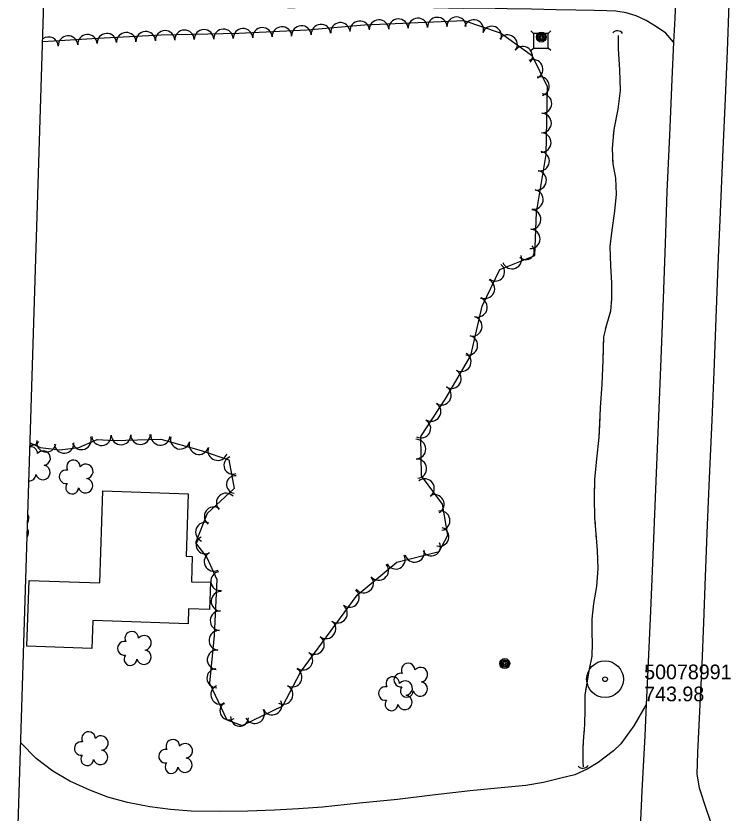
# Model space of a CAD drawing. Extents: x 591954 to 597000, y 198576 to 213500.
# Drawn here: x 593584.8 to 593879, y 199606.8 to 199932.5 of the extents above; entities that cross this region are included whole.
import ezdxf

# ---------------------------------------------------------------- set-up
doc = ezdxf.new("R2010")
doc.units = 0
for name, color, linetype in [('Level 11', 7, 'Continuous'), ('Level 12', 7, 'Continuous'), ('Level 14', 7, 'Continuous'), ('Level 15', 7, 'Continuous'), ('Level 17', 7, 'Continuous'), ('Level 18', 7, 'Continuous'), ('Level 19', 7, 'Continuous'), ('Level 21', 7, 'Continuous'), ('Level 4', 7, 'Continuous'), ('Level 6', 7, 'Continuous')]:
    doc.layers.add(name, color=color, linetype=linetype)

msp = doc.modelspace()

# ---------------------------------------------------------------- linework, layer by layer
at = {"layer": 'Level 11'}
for points in [[(593854.99, 199957.33), (593854.94, 199955.73), (593853.92, 199931.6), (593853.46, 199921.83)], [(593875.98, 199937.4), (593875.32, 199918.16), (593874.58, 199898.85), (593873.42, 199874.79), (593872.48, 199852.28), (593871.53, 199830.6), (593870.79, 199809.02), (593869.95, 199786.99), (593869.16, 199767.29), (593868.05, 199743.66), (593867.18, 199724.56), (593866.39, 199703.42), (593865.66, 199684.68), (593864.96, 199667.44), (593864, 199648.3), (593863.24, 199631.5), (593862.94, 199622.6)], [(593853.46, 199921.83), (593852.73, 199906.6), (593851.77, 199883.82), (593850.77, 199860.82), (593850.01, 199839.46), (593849.22, 199817.1), (593848.23, 199792.36), (593847.25, 199768.8), (593846.2, 199742.45), (593845.1, 199715.56), (593844.03, 199689.21), (593842.83, 199662.57), (593842.32, 199651.13)], [(593842.32, 199651.13), (593841.75, 199638.37), (593840.54, 199615.82), (593839.52, 199594.72), (593839.04, 199583.27)], [(593862.94, 199622.6), (593863.94, 199617.07), (593866.81, 199608.3), (593869.47, 199600.5), (593873.49, 199593.53), (593877.81, 199588.57), (593882.42, 199585.32), (593882.46, 199585.3)]]:
    msp.add_lwpolyline(points, dxfattribs=at)
at = {"layer": 'Level 12'}
msp.add_lwpolyline([(593620.24, 199738.41), (593655.16, 199737.27), (593654.32, 199711.75), (593656.79, 199711.67), (593656.45, 199701.32), (593664.27, 199701.07), (593663.9, 199690), (593655.29, 199690.28), (593655.09, 199684.16), (593624.17, 199685.17), (593624.17, 199685.17), (593616.14, 199685.43), (593615.77, 199674.07), (593589.25, 199674.94), (593590.13, 199701.81), (593619.01, 199700.86), (593620.24, 199738.41)], dxfattribs=at)
at = {"layer": 'Level 14'}
for centre, radius in [((593799.44, 199923.84), 2.02), ((593799.44, 199923.86), 1.52), ((593799.45, 199923.82), 1.01), ((593799.45, 199923.83), 0.502), ((593784.48, 199667.87), 2.02), ((593784.47, 199667.88), 1.52), ((593784.48, 199667.84), 1.01), ((593784.48, 199667.85), 0.502)]:
    msp.add_circle(centre, radius, dxfattribs=at)
at = {"layer": 'Level 15'}
for centre, start, end in [((593830.51, 199923.96), 32.1794, 138.419), ((593816.42, 199627.59), 220.1794, 326.419)]:
    msp.add_arc(centre, 2.5, start, end, dxfattribs=at)
at = {"layer": 'Level 17'}
for points in [[(593853.46, 199921.83), (593850.32, 199925.44), (593846.5, 199928.07), (593842.2, 199930.71), (593838.14, 199932.55), (593834.12, 199933.77), (593829.9, 199934.41), (593826.14, 199934.66), (593821.07, 199934.75), (593813.55, 199934.84), (593805.51, 199935.07), (593795.36, 199935.33), (593785.51, 199935.48), (593775.65, 199935.7), (593767.49, 199935.49), (593755.4, 199935.82), (593741.1, 199936.08), (593726.45, 199936.82), (593717.4, 199936.82), (593708.4, 199936.97), (593704.69, 199936.82), (593701.27, 199936.1), (593698.81, 199935.79), (593695.74, 199935.85)], [(593842.32, 199651.13), (593837.17, 199642.36), (593831.95, 199634.99), (593828.96, 199632.26), (593822.71, 199627.4), (593818.1, 199624.69), (593813.07, 199622.44), (593807.4, 199620.98), (593800.28, 199619.22), (593793.05, 199618.04), (593783.08, 199617.1), (593770.4, 199615.81), (593755.02, 199614.07), (593740.67, 199612.25), (593725.1, 199610.82), (593709.97, 199609.17), (593700.2, 199608.54), (593690.38, 199607.9), (593679.5, 199607.6), (593667.8, 199607.37), (593656.39, 199607.56), (593647.91, 199608.26), (593639.41, 199609.29), (593630.4, 199611.04), (593622.37, 199613.3), (593614.9, 199616.15), (593606.83, 199619.83), (593599.83, 199623.87), (593593.03, 199629.06), (593586.76, 199635.43)]]:
    msp.add_lwpolyline(points, dxfattribs=at)
at = {"layer": 'Level 18'}
msp.add_lwpolyline([(593590.58, 199758.12), (593594.65, 199756.14), (593602.64, 199755.24), (593610.52, 199756.21), (593617.93, 199759.42), (593624.95, 199759.05), (593643.97, 199759.54), (593660.45, 199754.93), (593671.69, 199751.16), (593673.94, 199739.4), (593662.95, 199729.21), (593658.12, 199717.22), (593662.79, 199711.25), (593666.8, 199702.17), (593665.78, 199679.28), (593663.89, 199659.85), (593670.87, 199644.91), (593677.17, 199642.52), (593693.84, 199650.58), (593701.08, 199664.38), (593724.14, 199695.77), (593740.37, 199709.29), (593757.72, 199713.6), (593761.29, 199720.35), (593759.01, 199733), (593750.49, 199744.57), (593750.23, 199760.62), (593760.28, 199776.05), (593770.63, 199793.68), (593775.27, 199813.84), (593782.45, 199828.94), (593796.74, 199834.59), (593797.42, 199852.18), (593801.39, 199875.9), (593801.9, 199903.55), (593795.83, 199916.03), (593782.72, 199925.49), (593767.93, 199930.48), (593752.2, 199929.85), (593727.22, 199928.78), (593703.58, 199926.68), (593675.82, 199925.38), (593644.04, 199924.59), (593618.17, 199923.29), (593595.69, 199921.88)], dxfattribs=at)
for centre, radius, start, end in [((593725.22, 199926.47), 3.98, 4.4854, 184.47), ((593733.09, 199926.95), 3.98, 2.4572, 182.4418), ((593741.04, 199927.29), 3.98, 2.45, 182.4347), ((593748.98, 199927.62), 3.98, 2.4428, 182.4275), ((593756.93, 199927.95), 3.98, 2.3201, 182.3048), ((593764.78, 199928.13), 3.95, 0.1381, 180.1228), ((593771.83, 199926.97), 3.98, 341.3586, 161.3433), ((593677.52, 199923.4), 3.98, 2.3058, 182.2904), ((593685.48, 199923.75), 3.98, 2.6877, 182.6724), ((593693.43, 199924.12), 3.98, 2.6809, 182.6655), ((593701.39, 199924.53), 3.98, 3.1859, 183.1706), ((593709.39, 199925.1), 3.98, 5.0913, 185.0759), ((593717.32, 199925.81), 3.98, 5.0919, 185.0766), ((593779.21, 199924.31), 3.96, 338.915, 158.8997), ((593598.1, 199919.94), 3.98, 3.5822, 126.5424), ((593606.04, 199920.44), 3.98, 3.5822, 183.5669), ((593613.98, 199920.94), 3.98, 3.5822, 183.5669), ((593621.9, 199921.39), 3.98, 2.933, 182.9177), ((593629.84, 199921.79), 3.98, 2.9039, 182.8886), ((593637.79, 199922.19), 3.98, 2.897, 182.8817), ((593645.7, 199922.52), 3.98, 1.8734, 181.8581), ((593653.63, 199922.75), 3.98, 1.4266, 181.4113), ((593661.59, 199922.94), 3.98, 1.4266, 181.4113), ((593669.54, 199923.14), 3.98, 1.4266, 181.4113), ((593785.65, 199920.8), 3.98, 324.1878, 144.1725), ((593791.86, 199916.1), 3.93, 321.1316, 141.1163), ((593796.08, 199910.74), 3.98, 295.9414, 115.9261), ((593798.82, 199903.79), 3.88, 286.1003, 106.0849), ((593799.69, 199896.69), 3.98, 268.9633, 88.948), ((593799.54, 199888.74), 3.98, 268.9633, 88.948), ((593799.4, 199880.78), 3.98, 268.9705, 88.9552), ((593798.76, 199873.15), 3.97, 261.4106, 81.3953), ((593797.51, 199865.33), 3.98, 260.4861, 80.4708), ((593796.19, 199857.48), 3.98, 260.4861, 80.4708), ((593795.29, 199849.36), 3.97, 266.8486, 86.8333), ((593794.92, 199841.39), 3.98, 267.8103, 87.795), ((593793.15, 199836.3), 3.4, 223.2258, 43.2104), ((593787.43, 199833.15), 3.98, 201.5871, 21.5717), ((593780.66, 199827.93), 3.76, 233.0615, 53.0462), ((593776.39, 199821.04), 3.98, 244.5892, 64.5739), ((593773.39, 199813.42), 3.96, 252.3469, 72.3315), ((593771.24, 199805.61), 3.98, 257.0422, 77.0269), ((593769.44, 199797.88), 3.97, 256.6656, 76.6503), ((593766.73, 199791.16), 3.98, 239.6071, 59.5918), ((593762.71, 199784.29), 3.98, 239.6133, 59.598), ((593758.64, 199777.51), 3.98, 238.4039, 58.3886), ((593754.41, 199770.84), 3.98, 236.9288, 56.9135), ((593750.33, 199763.92), 3.9, 241.4136, 61.3983), ((593619.72, 199760.88), 3.9, 183.9754, 3.96), ((593627.7, 199761.25), 3.98, 180.8074, 0.7921), ((593635.62, 199761.41), 3.98, 181.4842, 1.4689), ((593643.79, 199761.04), 3.93, 173.6659, 353.6505), ((593591.07, 199760.86), 3.8, 262.1684, 322.9777), ((593597.17, 199758.25), 3.94, 168.8719, 348.8566), ((593604.45, 199757.78), 3.96, 183.6012, 3.5858), ((593611.57, 199759.22), 3.95, 199.3285, 19.3132), ((593651.86, 199759.49), 3.98, 164.3502, 344.3348), ((593659.54, 199757.28), 3.98, 163.4844, 343.469), ((593748.23, 199755.52), 3.98, 270.9008, 90.8855), ((593590.84, 199753.66), 2.78, 1.3946, 96.3112), ((593595.88, 199751.8), 2.97, 278.4237, 139.6575), ((593667.19, 199754.86), 3.98, 161.5044, 341.4891), ((593673.4, 199748.89), 3.66, 110.8743, 290.859), ((593748.68, 199747.51), 3.9, 274.9806, 94.9653), ((593595.77, 199745.95), 2.97, 196.0745, 79.0477), ((593608.27, 199748.24), 2.78, 1.3946, 209.1675), ((593613.31, 199746.38), 2.97, 278.4237, 139.6575), ((593590.3, 199745.18), 2.61, 265.6293, 358.7123), ((593605.27, 199744.16), 2.78, 78.0716, 279.0826), ((593613.2, 199740.53), 2.97, 196.0745, 79.0477), ((593674.37, 199741.05), 3.56, 83.6773, 263.6619), ((593751.73, 199739.37), 3.98, 306.3734, 126.3581), ((593607.73, 199739.76), 2.61, 140.7797, 358.7123), ((593670.62, 199733.49), 3.98, 42.8327, 222.8173), ((593755.82, 199733.01), 3.89, 298.2431, 118.2277), ((593665.62, 199727.98), 3.88, 53.5789, 233.5636), ((593587.08, 199727.18), 2.97, 326.7838, 29.6455), ((593758.11, 199726.26), 3.98, 280.2455, 100.2302), ((593662.13, 199721.6), 3.98, 68.0953, 248.0799), ((593586.97, 199721.33), 2.97, 324.2134, 32.2158), ((593757.88, 199719.65), 3.79, 253.4068, 73.3915), ((593662.08, 199716.31), 3.65, 117.2505, 297.2352), ((593754.51, 199715.56), 3.71, 206.0377, 26.0224), ((593665.65, 199709.54), 3.96, 115.9681, 295.9527), ((593747.66, 199713.25), 3.98, 193.9356, 13.9203), ((593739.93, 199710.35), 3.88, 206.619, 26.6037), ((593732.98, 199705.85), 3.98, 219.8261, 39.8108), ((593668.24, 199701.55), 3.88, 97.9319, 277.9166), ((593726.87, 199700.76), 3.98, 219.8215, 39.8062), ((593668.49, 199693.32), 3.98, 87.443, 267.4277), ((593721.06, 199694.81), 3.96, 231.4325, 51.4172), ((593716.18, 199688.44), 3.98, 233.7039, 53.6886), ((593668.13, 199685.38), 3.98, 87.4427, 267.4274), ((593711.47, 199682.03), 3.98, 233.7039, 53.6886), ((593632.09, 199678.17), 2.78, 1.3946, 209.1675), ((593667.62, 199677.36), 3.98, 85.2985, 265.2831), ((593629.09, 199674.1), 2.78, 78.0716, 279.0826), ((593637.13, 199676.31), 2.97, 278.4237, 139.6575), ((593706.76, 199675.62), 3.98, 233.7039, 53.6886), ((593637.02, 199670.46), 2.97, 196.0745, 79.0477), ((593666.91, 199669.41), 3.98, 84.4748, 264.4595), ((593631.55, 199669.7), 2.61, 140.7797, 358.7123), ((593702.04, 199669.21), 3.98, 233.6981, 53.6828), ((593745, 199665.2), 2.78, 1.3946, 209.1675), ((593666.65, 199661.87), 3.87, 92.4972, 272.4819), ((593697.66, 199662.25), 3.98, 241.8245, 61.8092), ((593742, 199661.12), 2.78, 78.0716, 279.0826), ((593750.04, 199663.34), 2.97, 278.4237, 139.6575), ((593738.74, 199659.69), 2.78, 1.3946, 209.1675), ((593743.79, 199657.83), 2.97, 278.4237, 139.6575), ((593749.93, 199657.49), 2.97, 196.0745, 79.0477), ((593668.36, 199655.2), 3.98, 115.0685, 295.0532), ((593693.92, 199655.21), 3.98, 242.3474, 62.3321), ((593735.74, 199655.61), 2.78, 78.0716, 279.0826), ((593744.46, 199656.72), 2.61, 140.7797, 358.7123), ((593743.67, 199651.98), 2.97, 196.0745, 79.0477), ((593671.9, 199648.63), 3.8, 123.227, 303.2116), ((593689.45, 199650.81), 3.96, 206.4822, 26.4669), ((593738.21, 199651.21), 2.61, 140.7797, 358.7123), ((593682.34, 199647.33), 3.98, 205.8029, 25.7876), ((593676.16, 199645.96), 3.68, 175.0167, 355.0014), ((593614.43, 199637.23), 2.78, 1.3946, 209.1675), ((593619.47, 199635.37), 2.97, 278.4237, 139.6575), ((593611.43, 199633.15), 2.78, 78.0716, 279.0826), ((593648.88, 199634.05), 2.78, 1.3946, 209.1675), ((593653.92, 199632.2), 2.97, 278.4237, 139.6575), ((593619.36, 199629.52), 2.97, 196.0745, 79.0477), ((593645.88, 199629.98), 2.78, 78.0716, 279.0826), ((593613.89, 199628.76), 2.61, 140.7797, 358.7123), ((593653.81, 199626.34), 2.97, 196.0745, 79.0477), ((593648.34, 199625.58), 2.61, 140.7797, 358.7123)]:
    msp.add_arc(centre, radius, start, end, dxfattribs=at)
at = {"layer": 'Level 19'}
for points in [[(593830.76, 199924.45), (593830.83, 199919.06), (593831.36, 199910.45), (593831.68, 199902.1), (593830.71, 199894.46), (593829.02, 199886.11), (593828.36, 199878.35), (593828.65, 199872.12), (593829.69, 199866.27), (593830.05, 199859.74), (593829.26, 199852.72), (593828.23, 199844.91), (593827.47, 199838.26), (593827.71, 199830.45), (593828.06, 199823.4), (593828.16, 199817.1), (593827.64, 199811.89), (593826, 199806.27), (593824.81, 199801.41), (593824.5, 199791.66), (593824.2, 199782.1), (593823.52, 199772.35), (593822.88, 199760.24), (593821.96, 199751.56), (593821.17, 199743.11), (593820.96, 199735.52), (593821.2, 199727.44), (593821.66, 199721.04), (593822.3, 199714.05), (593822.57, 199706.75), (593821.99, 199699.41), (593820.74, 199692.46), (593820.06, 199686.04), (593820.03, 199680.45), (593820.21, 199676.19), (593820.01, 199670.87), (593818.82, 199664.85), (593817.89, 199659.06), (593817.2, 199655.02), (593817.2, 199649.2), (593817.09, 199642.78), (593816.71, 199637.87), (593816.45, 199633.76), (593816.45, 199627.39), (593816.53, 199625.65)], [(593830.76, 199924.45), (593830.83, 199919.06), (593831.36, 199910.45), (593831.68, 199902.1), (593830.84, 199895.52)], [(593830.13, 199891.59), (593829.73, 199889.63)], [(593828.99, 199885.7), (593828.82, 199883.71)], [(593828.47, 199879.73), (593828.36, 199878.35), (593828.39, 199877.73)], [(593828.57, 199873.74), (593828.65, 199872.12), (593829.69, 199866.27), (593830.05, 199859.74), (593829.26, 199852.72), (593828.23, 199844.95)], [(593828.23, 199844.95), (593828.23, 199844.91), (593827.47, 199838.26), (593827.71, 199830.45), (593828.06, 199823.4), (593828.16, 199817.1), (593828.05, 199816.01)], [(593827.65, 199812.03), (593827.64, 199811.89), (593827.12, 199810.11)], [(593826, 199806.27), (593826, 199806.27), (593825.53, 199804.33)], [(593824.78, 199800.41), (593824.72, 199798.41)], [(593824.59, 199794.41), (593824.5, 199791.66), (593824.2, 199782.1), (593823.52, 199772.35), (593823.16, 199765.45)], [(593823.16, 199765.45), (593822.88, 199760.24), (593821.96, 199751.56), (593821.17, 199743.11), (593820.99, 199736.55)], [(593821.05, 199732.55), (593821.11, 199730.55)], [(593821.26, 199726.55), (593821.41, 199724.56)], [(593821.7, 199720.57), (593821.88, 199718.58)], [(593822.25, 199714.6), (593822.3, 199714.05), (593822.57, 199706.75), (593821.99, 199699.41), (593820.74, 199692.46), (593820.06, 199686.04), (593820.06, 199685.77)], [(593820.06, 199685.77), (593820.03, 199680.45), (593820.21, 199676.19), (593820.01, 199670.87), (593818.82, 199664.85), (593817.89, 199659.06), (593817.54, 199657)], [(593817.2, 199653.03), (593817.2, 199651.03)], [(593817.16, 199647.03), (593817.13, 199645.03)], [(593816.96, 199641.04), (593816.8, 199639.04)], [(593816.53, 199635.05), (593816.45, 199633.76), (593816.45, 199627.39), (593816.53, 199625.65)]]:
    msp.add_lwpolyline(points, dxfattribs=at)
at = {"layer": 'Level 21'}
for p, q in [((593796.22, 199925.4), (593795.16, 199926.46)), ((593802.22, 199925.4), (593803.28, 199926.46)), ((593795.16, 199918.34), (593796.22, 199919.4)), ((593803.28, 199918.34), (593802.22, 199919.4))]:
    msp.add_line(p, q, dxfattribs=at)
msp.add_lwpolyline([(593796.22, 199919.4), (593802.22, 199919.4), (593802.22, 199925.4), (593796.22, 199925.4)], close=True, dxfattribs=at)
at = {"layer": 'Level 4'}
msp.add_lwpolyline([(593584.77, 199571.41), (593613.48, 200492.57), (593612.63, 200492.46)], dxfattribs=at)
at = {"layer": 'Level 6'}
for radius in [7.5, 0.96]:
    msp.add_circle((593825.45, 199661.45), radius, dxfattribs=at)

# ---------------------------------------------------------------- texts
for s, p in [('50078991', (593841.45, 199661.45)), ('743.98', (593841.45, 199652.45))]:
    msp.add_text(s, height=6, dxfattribs=at).set_placement(p)

doc.saveas('drawing.dxf')
